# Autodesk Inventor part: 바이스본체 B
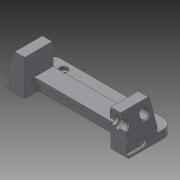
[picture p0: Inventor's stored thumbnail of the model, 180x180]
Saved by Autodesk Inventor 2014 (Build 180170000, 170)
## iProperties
Created: 2017-04
Part Number: 바이스본체 B
Material: 알루미늄 6061
Document SubType Name: Modeling
Designer: mduedu
Density: 2.71 g/cm^3
Appearance: 기본값
Author: mduedu
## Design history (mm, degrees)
sketch "스케치1"
  geometry: L1 (-75, 0)-(75, 0); L2 (-75, 0)-(-75, 17); L3 (-53, 17)-(53, 17); L4 (75, 17)-(75, 0); L5 (-75, 17)-(-65.173, 44); L6 (-65.173, 44)-(-53, 44); L7 (-53, 44)-(-53, 17); L8 (0, 0)-(0, 17); L9 (75, 17)-(65.173, 44); L10 (65.173, 44)-(53, 44); L11 (53, 44)-(53, 17); 1 further point
  constraints: 22 end point, 4 perpendicular, 2 horizontal alignment, 2 midpoint, 2 symmetric about line, 1 coincident, 1 collinear, 1 horizontal, 1 vertical
  dimensions: "d0" = 150 distance of L1.start L1.end; "d1" = 17 distance of L1.start L2.end; "d2" = 27 distance of L3.start L6.end; "d3" = 22 distance of L3.start L2.end; "d4" = 70 deg angle of L3 L5; "d54" = 20 deg angle of L9 L4
extrude "돌출1" new body sketch "스케치1" stored distance "d5" = 70; taper "d6" = 0 deg
sketch "스케치2"
  geometry: L1 (0, 70)-(106, 70) reference; L2 (106, 70)-(106, 0) reference; L3 (106, 0)-(0, 0) reference; L4 (0, 47)-(106, 47); L5 (106, 47)-(106, 23); L6 (106, 23)-(0, 23); L7 (0, 23)-(0, 47); L8 (0, 70)-(0, 0) reference; 2 further points
  constraints: 8 end point, 2 parallel, 2 point on line, 1 horizontal, 1 horizontal alignment, 1 midpoint, 1 perpendicular
  dimensions: "d7" = 24 distance between parallel lines of L6 L4
extrude "돌출2" cut sketch "스케치2" stored distance "d9" = 70; taper "d10" = 0 deg
sketch "스케치3"
  geometry: L1 (22, -23)-(128, -23) reference; L2 (128, -47)-(22, -47) reference; L3 (22, -18)-(128, -18); L4 (128, -52)-(22, -52); L5 (22, -18)-(22, -52); L6 (128, -18)-(128, -52); 1 further point
  constraints: 8 end point, 3 parallel, 2 point on line, 1 perpendicular
  dimensions: "d11" = 5 distance between parallel lines of L3 L1; "d12" = 5 distance between parallel lines of L4 L2
extrude "돌출3" cut sketch "스케치3" distance "d13" = 12; taper "d14" = 0 deg
fillet "모깎기1" dims "d15" = 3, "d16" = 3
sketch "스케치4"
  geometry: L1 (103, 23)-(3, 23) reference; L2 (0, 26)-(0, 0) reference; L3 (106, 0)-(0, 0) reference; L4 (106, 26)-(106, 0) reference; L5 (96, 0)-(90, 0); L6 (90, 0)-(90, 19.5); L7 (96, 19.5)-(96, 0); L8 (90, 19.5)-(96, 19.5); A1 r 3 centre (3, 26) between (0, 26) and (3, 23) reference; A2 r 3 centre (103, 26) between (103, 23) and (106, 26) reference; 1 further point
  constraints: 8 end point, 2 perpendicular, 1 horizontal, 1 parallel, 1 point on line
  dimensions: "d17" = 10 distance between parallel lines of L7 L4; "d18" = 6 distance between parallel lines of L7 L6; "d27" = 3.5 distance between parallel lines of L8 L1
extrude "돌출4" join sketch "스케치4" distance "d19" = 12; taper "d20" = 0 deg
chamfer "모따기1" distance "d21" = 3; stored, may be unused: second distance "d22" = 2, angle "d23" = 45 deg
chamfer "모따기2" distance "d24" = 3; stored, may be unused: second distance "d25" = 2, angle "d26" = 45 deg
sketch "스케치5"
  geometry: L1 (-15.5, 35.8)-(-15.5, -25.8) reference; L2 (19.5, 0)-(0, 0) reference; C1 r 6.5 at (9.5, 15); 1 further point
  constraints: 1 centre point
  dimensions: "d28" = 13 diameter of C1; "d30" = 15 distance from line of C1.centre L2; "d31" = 25 distance from line of C1.centre L1
extrude "돌출5" cut sketch "스케치5" stored distance "d32" = 12; taper "d33" = 0 deg
sketch "스케치6"
  geometry: C1 r 5 at (-10, 15); C2 r 5 at (-60, 15); A1 r 6.5 centre (-10, 15) between (-15.766, 12) and (-4.234, 12) reference; A2 r 6.5 centre (-60, 15) between (-65.766, 12) and (-54.234, 12) reference; 1 further point
  constraints: 2 centre point, 2 coincident
  dimensions: "d34" = 10 diameter of C1; "d35" = 10 diameter of C2 (= d34)
extrude "돌출6" cut sketch "스케치6" stored distance "d36" = 12; taper "d37" = 0 deg
chamfer "모따기3" distance "d38" = 1; stored, may be unused: second distance "d39" = 2, angle "d40" = 45 deg
chamfer "모따기4" distance "d41" = 1; stored, may be unused: second distance "d42" = 2, angle "d43" = 45 deg
sketch "스케치7"
  geometry: L1 (-35, 35.8)-(-35, -25.8) reference; L2 (-70, 0)-(0, 0) reference; C1 r 5 at (-35, 15); 1 further point
  constraints: 1 centre point, 1 point on line
  dimensions: "d44" = 10 diameter of C1; "d45" = 15 distance from line of C1.centre L2
extrude "돌출7" cut sketch "스케치7" stored distance "d46" = 12; taper "d47" = 0 deg
chamfer "모따기5" distance "d48" = 1; stored, may be unused: second distance "d49" = 2, angle "d50" = 45 deg
node "작업축1"
sketch "스케치8"
  geometry: L1 (-105, 32)-(105, 32) reference; L2 (58, 32)-(64, 32); L3 (64, 32)-(64, 40); L4 (64, 40)-(58, 40); L5 (58, 40)-(58, 32); L6 (53, 38)-(53, 26) reference; 1 further point
  constraints: 8 end point, 2 parallel, 1 horizontal, 1 perpendicular, 1 point on line
  dimensions: "d51" = 5 distance from line of L6 L2.start; "d52" = 6 distance of L3.end L4.end; "d53" = 16 diameter of L4 L1
revolve "회전1" sketch "스케치8" stored, may be unused: angle "d55" = 90 deg
fillet "모깎기2"
chamfer "모따기6" distance "d56" = 1; stored, may be unused: second distance "d57" = 2, angle "d58" = 45 deg
sketch "스케치9"
  geometry: L1 (17.5, 3)-(52.5, 3); L2 (52.5, 13)-(17.5, 13); L3 (70, 0)-(0, 0) reference; L4 (17.5, 8)-(52.5, 8); A1 r 5 centre (17.5, 8) between (17.5, 13) and (17.5, 3); A2 r 5 centre (52.5, 8) between (52.5, 3) and (52.5, 13); 3 further points
  constraints: 6 end point, 4 point on circle, 3 tangent, 2 centre point, 2 midpoint, 2 parallel, 1 horizontal, 1 vertical alignment
  dimensions: "d59" = 35 distance of L4.start L4.end; "d61" = 5 radius of A2; "d62" = 8 distance between parallel lines of L3 L4
extrude "돌출8" cut sketch "스케치9" distance "d63" = 3; taper "d64" = 0 deg
chamfer "모따기7" distance "d65" = 1; stored, may be unused: second distance "d66" = 2, angle "d67" = 45 deg
chamfer "모따기8" distance "d68" = 1; stored, may be unused: second distance "d69" = 2, angle "d70" = 45 deg
feature "분할1"
sketch "스케치10"
  geometry: A1 r 5 centre (0, 0) between (0, 5) and (0, -5) reference; 1 further point
  constraints: 1 coincident
hole "구멍1" sketch "스케치10" at (0, 0) diameter "d71" = 2.459; stored, may be unused: countersink angle "d75" = 90 deg, drill point angle "d77" = 120 deg; dims "d72" = 4.5, "d73" = 4, "d74" = 2, "d76" = 6
sketch "스케치11"
  geometry: L1 (0, 0)-(0, 27) reference; L2 (0, 27)-(-35, 27) reference; 2 further points
  dimensions: "d78" = 12 distance from line of point (-12, 15.5) L1; "d79" = 11.5 distance from line of point (-12, 15.5) L2
hole "구멍2" sketch "스케치11" at (-12, 15.5) diameter "d80" = 3.242; stored, may be unused: countersink angle "d84" = 90 deg, drill point angle "d86" = 120 deg; dims "d81" = 6, "d82" = 4, "d83" = 2, "d85" = 8
sketch "스케치12"
  geometry: L1 (-75, -35)-(-75, 0) reference; L2 (75, -35)-(75, 0) reference; L3 (75, -35)-(-75, -35); L4 (-75, -35)-(-75, -55); L5 (-75, -55)-(75, -55); L6 (75, -55)-(75, -35); 1 further point
  constraints: 8 end point, 2 parallel, 1 horizontal, 1 perpendicular, 1 point on line
  dimensions: "d87" = 20 distance of L3.end L4.end; "d89" = 150 distance of L4.end L5.end (derived)
extrude "돌출9" join sketch "스케치12" distance "d90" = 10; taper "d91" = 0 deg
sketch "스케치13"
  geometry: L1 (-75, 55)-(-75, 35) reference; L2 (75, 35)-(75, 55) reference; L3 (-75, 45)-(75, 45); 3 further points
  constraints: 2 end point, 2 midpoint, 2 point on line
  dimensions: "d92" = 50 horizontal distance of point (-50, 45) point (0, 0); "d93" = 100 distance of point (50, 45) point (-50, 45)
fillet "모깎기3" dims "d94" = 12
chamfer "모따기9" distance "d95" = 1; stored, may be unused: second distance "d96" = 2, angle "d97" = 45 deg
hole "구멍3" sketch "스케치13" diameter "d98" = 4.134; stored, may be unused: countersink angle "d102" = 90 deg, drill point angle "d104" = 118 deg; dims "d99" = 6, "d100" = 10, "d101" = 4, "d103" = 8
node "솔리드1"
mirror "대칭1"
mirror "대칭2"
mirror "대칭3"
mirror "대칭4"
node "투영된 루프1"
